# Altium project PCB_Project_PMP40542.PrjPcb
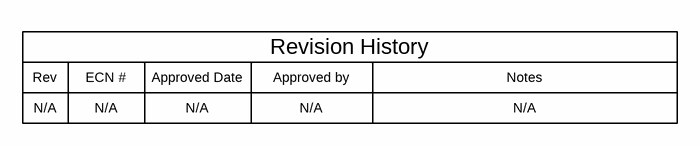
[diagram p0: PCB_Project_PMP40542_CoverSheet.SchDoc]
CopyrightYear: 2018; PCB_Layout: San Chen; PCB_Rev: E1; PRJ_Customer: Public Release; PRJ_Engineer: San Chen; PRJ_Number: PMP40542; PRJ_Title: 6~36V in, Type-C+Type-C Charger; SCH_Rev: E1; TechSupport: http://www.ti.com/support; TID: N/A
2 sheets, 62 parts. Net scope: flat (ports and power ports of the same name join across sheets).
Board file: PCB_Project_PMP40542_PCB.PcbDoc
Sheets:
  PCB_Project_PMP40542_CoverSheet.SchDoc
  PCB_Project_PMP40542_BlankSheet.SchDoc

## Sheet PCB_Project_PMP40542_CoverSheet.SchDoc
size 431 x 279 mm; Date: Not shown in title block; ApprovedBy: Not shown in title block; CheckedBy: Not shown in title block; Author: Not shown in title block; CompanyName: Not shown in title block; Engineer: Not shown in title block; Organization: Not shown in title block; Address1: Not shown in title block; Address2: Not shown in title block; Address3: Not shown in title block; Address4: Not shown in title block; DocumentNumber: 1; Revision: Use project parameter SCH_Rev; SheetNumber: 1; SheetTotal: 2; PageSetup: Record=PageOptions¦CenterHorizontal=True¦CenterVertical=True¦PrintScale=1.00¦XCorrection=1.00¦YCorrection=1.00¦PrintKind=0¦BorderSize=5000000¦LeftOffset=0¦BottomOffset=0¦Orientation=2¦PaperLength=1000¦PaperWidth=1000¦Scale=100¦PaperSource=15¦PrintQuality=600¦MediaType=1¦DitherType=10¦PaperKind=Letter¦PrintScaleMode=1

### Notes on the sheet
- Rev
- N/A
- ECN #
- Approved Date
- Approved by
- Revision History
- Notes

## Sheet PCB_Project_PMP40542_BlankSheet.SchDoc
size 431 x 279 mm; Date: Not shown in title block; ApprovedBy: Not shown in title block; CheckedBy: Not shown in title block; Author: Not shown in title block; CompanyName: Not shown in title block; Engineer: Not shown in title block; Organization: Not shown in title block; Address1: Not shown in title block; Address2: Not shown in title block; Address3: Not shown in title block; Address4: Not shown in title block; DocumentNumber: 1; Revision: Use project parameter SCH_Rev; SheetNumber: 2; SheetTotal: 2; PageSetup: Record=PageOptions¦CenterHorizontal=True¦CenterVertical=True¦PrintScale=1.00¦XCorrection=1.00¦YCorrection=1.00¦PrintKind=0¦BorderSize=5000000¦LeftOffset=0¦BottomOffset=0¦Orientation=2¦PaperLength=1000¦PaperWidth=1000¦Scale=100¦PaperSource=15¦PrintQuality=600¦MediaType=1¦DitherType=10¦PaperKind=Letter¦PrintScaleMode=1
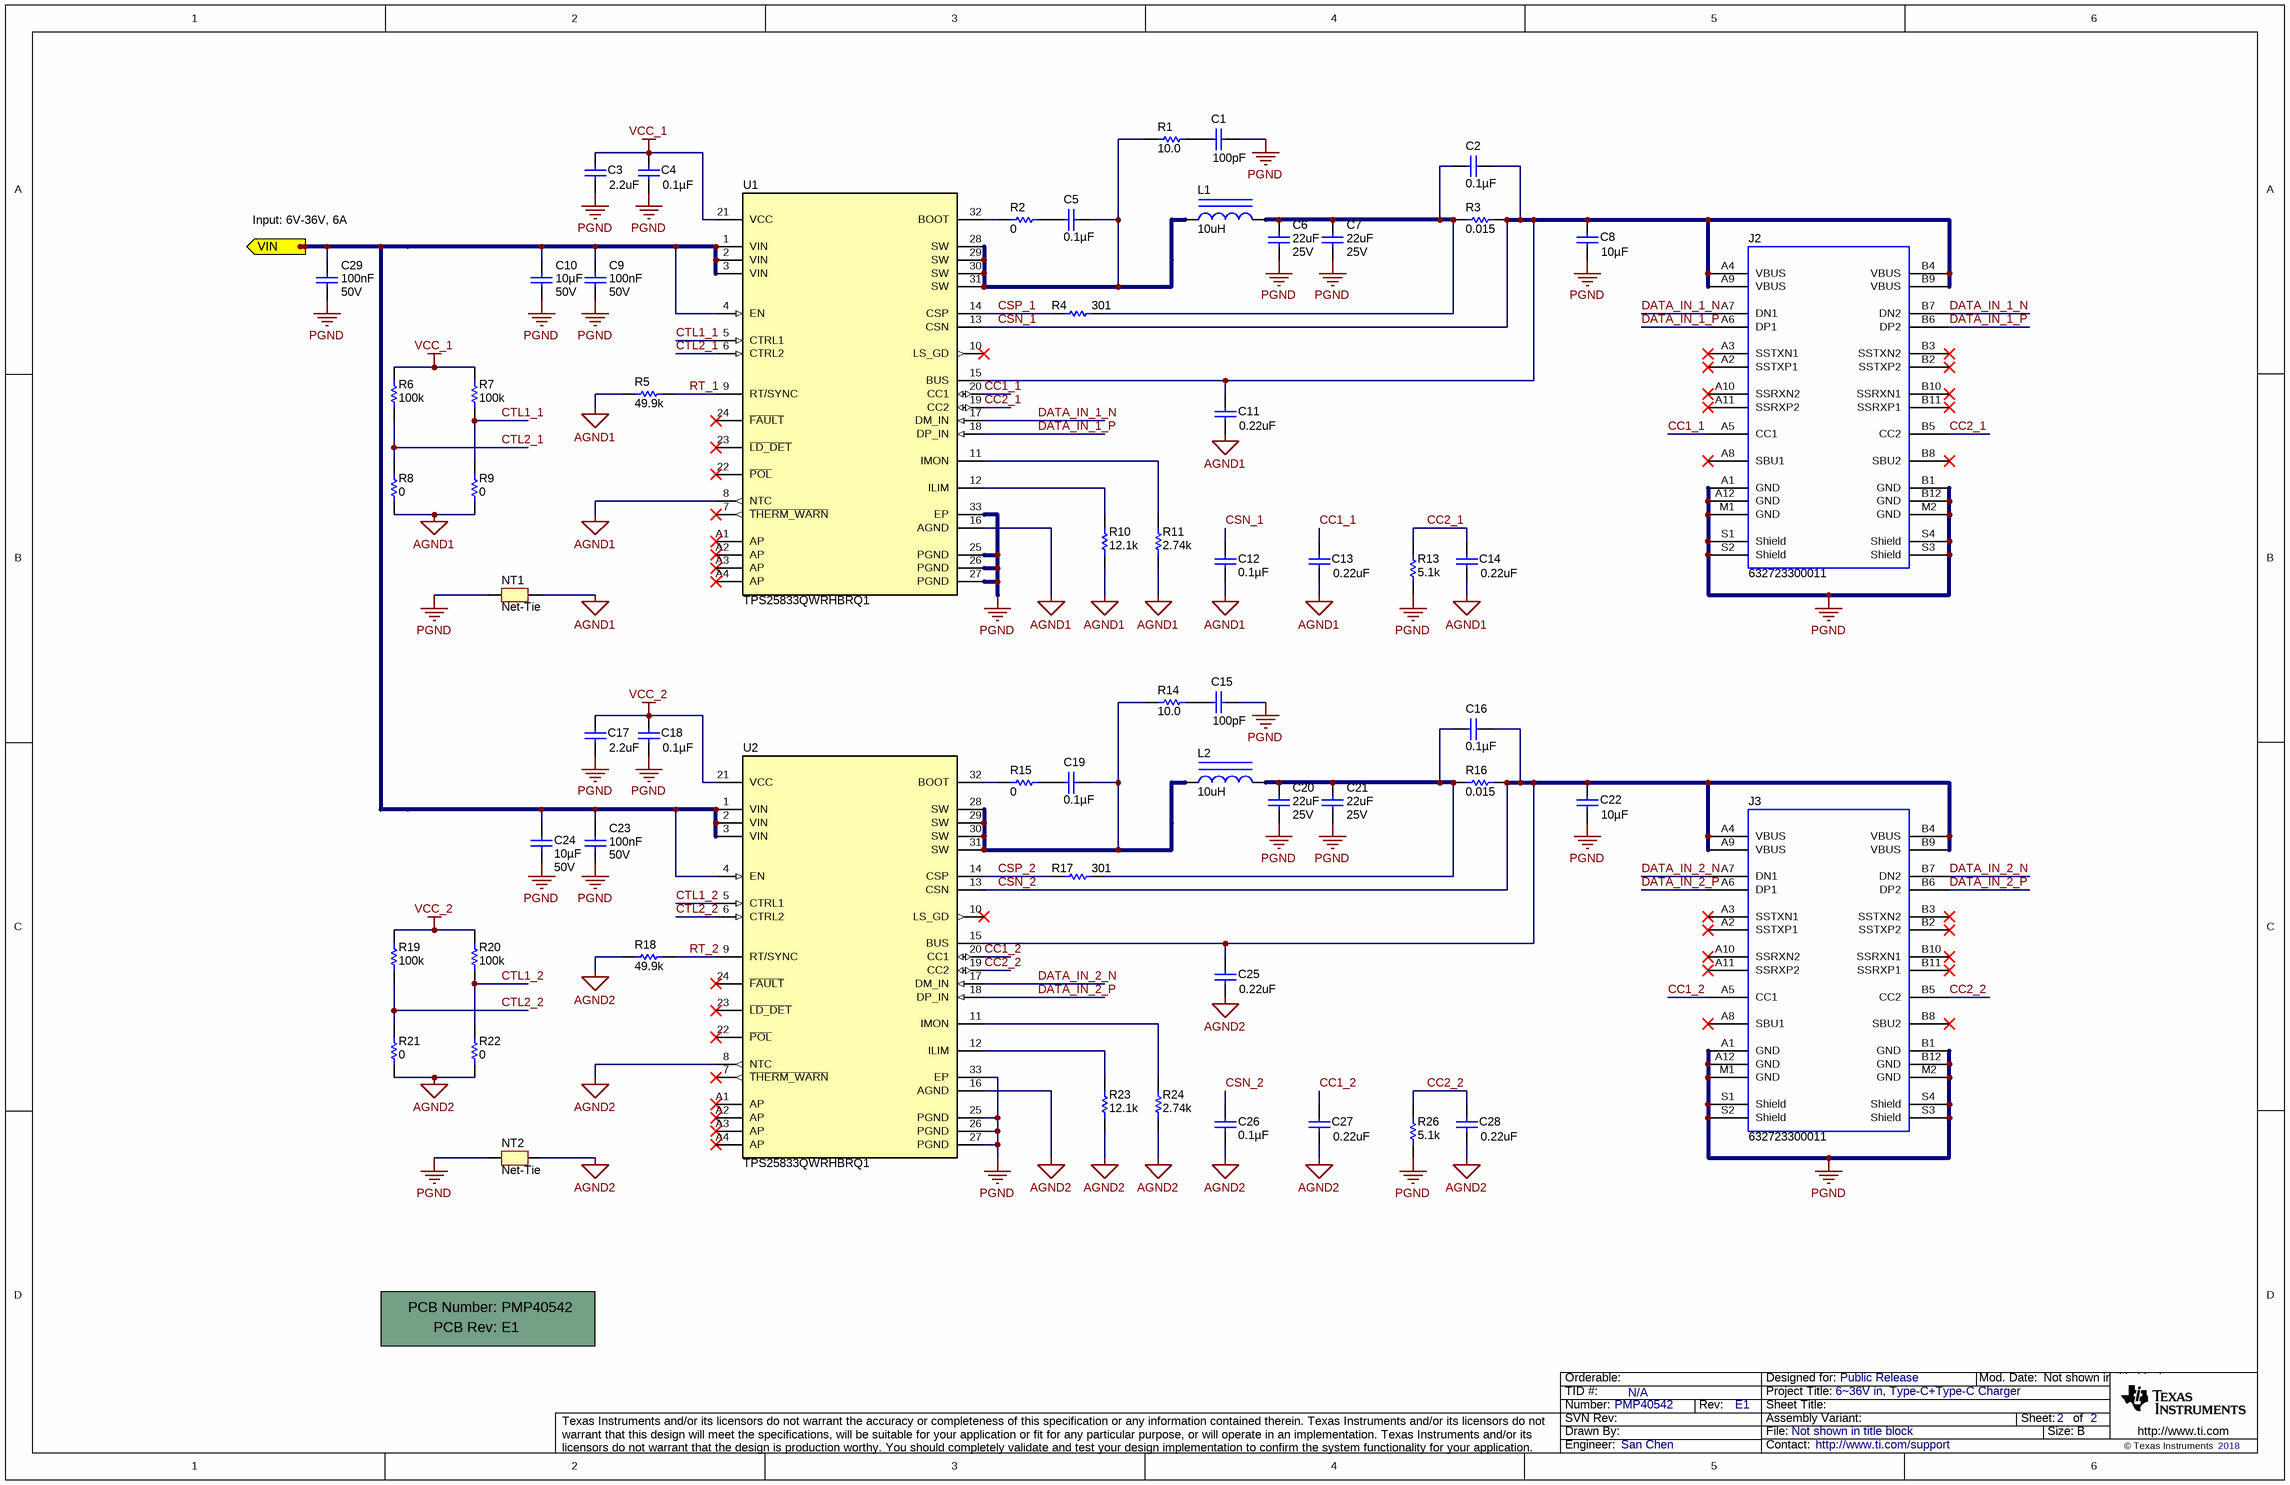
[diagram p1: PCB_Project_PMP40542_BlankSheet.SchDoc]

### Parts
!PCB  Printed Circuit Board  (value not drawn)  (mechanical)
C1  ValueDisplayed: 100pF  [0603]  (hidden comment: GCM1885C2A101JA16D)
C2  ValueDisplayed: 0.1µF  [0402]  (hidden comment: CGA2B3X7R1E104K050BB)
C3  ValueDisplayed: 2.2uF  [0402]  (hidden comment: GRT155R61E225KE13D)
C4  ValueDisplayed: 0.1µF  [0402]  (hidden comment: CGA2B3X7R1E104K050BB)
C5  ValueDisplayed: 0.1µF  [0402]  (hidden comment: CGA2B3X7R1E104K050BB)
C6  VDC_V: 25V  ValueDisplayed: 22uF  [1206_180]  (hidden comment: GRT31CR61E226KE01L)
C7  VDC_V: 25V  ValueDisplayed: 22uF  [1206_180]  (hidden comment: GRT31CR61E226KE01L)
C8  ValueDisplayed: 10µF  [0805_HV]  (hidden comment: GRM21BC81C106KA73L)
C9  Cap_F: 100nF  VDC_V: 50V  [0603]  (hidden comment: CGA3E2X7R1H104K080AA)
C10  ValueDisplayed: 10µF  VDC_V: 50V  [1206_190]  (hidden comment: CGA5L1X7R1H106K160AC)
C11  ValueDisplayed: 0.22uF  [0402]  (hidden comment: C1005X5R1E224M050BC)
C12  ValueDisplayed: 0.1µF  [0402]  (hidden comment: CGA2B3X7R1E104K050BB)
C13  ValueDisplayed: 0.22uF  [0402]  (hidden comment: C1005X5R1E224M050BC)
C14  ValueDisplayed: 0.22uF  [0402]  (hidden comment: C1005X5R1E224M050BC)
C15  ValueDisplayed: 100pF  [0603]  (hidden comment: GCM1885C2A101JA16D)
C16  ValueDisplayed: 0.1µF  [0402]  (hidden comment: CGA2B3X7R1E104K050BB)
C17  ValueDisplayed: 2.2uF  [0402]  (hidden comment: GRT155R61E225KE13D)
C18  ValueDisplayed: 0.1µF  [0402]  (hidden comment: CGA2B3X7R1E104K050BB)
C19  ValueDisplayed: 0.1µF  [0402]  (hidden comment: CGA2B3X7R1E104K050BB)
C20  VDC_V: 25V  ValueDisplayed: 22uF  [1206_180]  (hidden comment: GRT31CR61E226KE01L)
C21  VDC_V: 25V  ValueDisplayed: 22uF  [1206_180]  (hidden comment: GRT31CR61E226KE01L)
C22  ValueDisplayed: 10µF  [0805_HV]  (hidden comment: GRM21BC81C106KA73L)
C23  Cap_F: 100nF  VDC_V: 50V  [0603]  (hidden comment: CGA3E2X7R1H104K080AA)
C24  ValueDisplayed: 10µF  VDC_V: 50V  [1206_190]  (hidden comment: CGA5L1X7R1H106K160AC)
C25  ValueDisplayed: 0.22uF  [0402]  (hidden comment: C1005X5R1E224M050BC)
C26  ValueDisplayed: 0.1µF  [0402]  (hidden comment: CGA2B3X7R1E104K050BB)
C27  ValueDisplayed: 0.22uF  [0402]  (hidden comment: C1005X5R1E224M050BC)
C28  ValueDisplayed: 0.22uF  [0402]  (hidden comment: C1005X5R1E224M050BC)
C29  Cap_F: 100nF  VDC_V: 50V  [0603]  (hidden comment: CGA3E2X7R1H104K080AA)
J2  632723300011  [Wurth_632_723_300_011]
J3  632723300011  [Wurth_632_723_300_011]
L1  ValueDisplayed: 10uH  [XAL6060]  (hidden comment: XAL6060-103MEB)
L2  ValueDisplayed: 10uH  [XAL6060]  (hidden comment: XAL6060-103MEB)
NT1  Net-Tie  [Net-Tie_10milWide_30milLong]  (net tie, no BOM)
NT2  Net-Tie  [Net-Tie_10milWide_30milLong]  (net tie, no BOM)
R1  ValueDisplayed: 10.0  [1206]  (hidden comment: ERJ-8ENF10R0V)
R2  ValueDisplayed: 0  [0402]  (hidden comment: ERJ-2GE0R00X)
R3  ValueDisplayed: 0.015  [1206]  (hidden comment: CSR1206FK15L0)
R4  ValueDisplayed: 301  [0402]  (hidden comment: CRCW0402301RFKED)
R5  ValueDisplayed: 49.9k  [0402]  (hidden comment: ERJ-2RKF4992X)
R6  ValueDisplayed: 100k  [0402]  (hidden comment: CRCW0402100KFKED)
R7  ValueDisplayed: 100k  [0402]  (hidden comment: CRCW0402100KFKED)
R8  ValueDisplayed: 0  [0402]  (hidden comment: ERJ-2GE0R00X)
R9  ValueDisplayed: 0  [0402]  (hidden comment: ERJ-2GE0R00X)
R10  ValueDisplayed: 12.1k  [0402]  (hidden comment: CRCW040212K1FKED)
R11  ValueDisplayed: 2.74k  [0402]  (hidden comment: CRCW04022K74FKED)
R13  ValueDisplayed: 5.1k  [0402]  (hidden comment: CRCW04025K10JNED)
R14  ValueDisplayed: 10.0  [1206]  (hidden comment: ERJ-8ENF10R0V)
R15  ValueDisplayed: 0  [0402]  (hidden comment: ERJ-2GE0R00X)
R16  ValueDisplayed: 0.015  [1206]  (hidden comment: CSR1206FK15L0)
R17  ValueDisplayed: 301  [0402]  (hidden comment: CRCW0402301RFKED)
R18  ValueDisplayed: 49.9k  [0402]  (hidden comment: ERJ-2RKF4992X)
R19  ValueDisplayed: 100k  [0402]  (hidden comment: CRCW0402100KFKED)
R20  ValueDisplayed: 100k  [0402]  (hidden comment: CRCW0402100KFKED)
R21  ValueDisplayed: 0  [0402]  (hidden comment: ERJ-2GE0R00X)
R22  ValueDisplayed: 0  [0402]  (hidden comment: ERJ-2GE0R00X)
R23  ValueDisplayed: 12.1k  [0402]  (hidden comment: CRCW040212K1FKED)
R24  ValueDisplayed: 2.74k  [0402]  (hidden comment: CRCW04022K74FKED)
R26  ValueDisplayed: 5.1k  [0402]  (hidden comment: CRCW04025K10JNED)
U1  TPS25833QWRHBRQ1  [RHB0032R]
U2  TPS25833QWRHBRQ1  [RHB0032R]

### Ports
VIN (in)

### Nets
AGND1: C11.2 C12.1 C13.2 C14.2 NT1.2 R5.1 R8.1 R9.1 R10.1 R11.1 U1.8(NTC) U1.16(AGND)
AGND2: C25.2 C26.1 C27.2 C28.2 NT2.2 R18.1 R21.1 R22.1 R23.1 R24.1 U2.8(NTC) U2.16(AGND)
PGND: C1.1 C3.2 C4.2 C6.2 C7.2 C8.2 C9.2 C10.2 C15.1 C17.2 C18.2 C20.2 C21.2 C22.2 C23.2 C24.2 C29.2 J2.A1(GND) J2.A12(GND) J2.B1(GND) J2.B12(GND) J2.M1(GND) J2.M2(GND) J2.S1(Shield) J2.S2(Shield) J2.S3(Shield) J2.S4(Shield) J3.A1(GND) J3.A12(GND) J3.B1(GND) J3.B12(GND) J3.M1(GND) J3.M2(GND) J3.S1(Shield) J3.S2(Shield) J3.S3(Shield) J3.S4(Shield) NT1.1 NT2.1 R13.1 R26.1 U1.25(PGND) U1.26(PGND) U1.27(PGND) U1.33(EP) U2.25(PGND) U2.26(PGND) U2.27(PGND) U2.33(EP)
VCC_1: C3.1 C4.1 R6.2 R7.2 U1.21(VCC)
VCC_2: C17.1 C18.1 R19.2 R20.2 U2.21(VCC)
CC1_1: C13.1 J2.A5(CC1) U1.20(CC1)
CC1_2: C27.1 J3.A5(CC1) U2.20(CC1)
CC2_1: C14.1 J2.B5(CC2) R13.2 U1.19(CC2)
CC2_2: C28.1 J3.B5(CC2) R26.2 U2.19(CC2)
CSN_1: C2.2 C8.1 C11.1 C12.2 J2.A4(VBUS) J2.A9(VBUS) J2.B4(VBUS) J2.B9(VBUS) R3.2 U1.13(CSN) U1.15(BUS)
CSN_2: C16.2 C22.1 C25.1 C26.2 J3.A4(VBUS) J3.A9(VBUS) J3.B4(VBUS) J3.B9(VBUS) R16.2 U2.13(CSN) U2.15(BUS)
CSP_1: R4.1 U1.14(CSP)
CSP_2: R17.1 U2.14(CSP)
CTL1_1: R7.1 R9.2 U1.5(CTRL1)
CTL1_2: R20.1 R22.2 U2.5(CTRL1)
CTL2_1: R6.1 R8.2 U1.6(CTRL2)
CTL2_2: R19.1 R21.2 U2.6(CTRL2)
DATA_IN_1_N: J2.A7(DN1) J2.B7(DN2) U1.17(DM_IN)
DATA_IN_1_P: J2.A6(DP1) J2.B6(DP2) U1.18(DP_IN)
DATA_IN_2_N: J3.A7(DN1) J3.B7(DN2) U2.17(DM_IN)
DATA_IN_2_P: J3.A6(DP1) J3.B6(DP2) U2.18(DP_IN)
RT_1: R5.2 U1.9(RT/SYNC)
RT_2: R18.2 U2.9(RT/SYNC)
VIN: C9.1 C10.1 C23.1 C24.1 C29.1 U1.1(VIN) U1.2(VIN) U1.3(VIN) U1.4(EN) U2.1(VIN) U2.2(VIN) U2.3(VIN) U2.4(EN) ; port VIN
NetC1_2: C1.2 R1.2
NetC2_1: C2.1 C6.1 C7.1 L1.2 R3.1 R4.2
NetC5_1: C5.1 R2.2
NetC5_2: C5.2 L1.1 R1.1 U1.28(SW) U1.29(SW) U1.30(SW) U1.31(SW)
NetC15_2: C15.2 R14.2
NetC16_1: C16.1 C20.1 C21.1 L2.2 R16.1 R17.2
NetC19_1: C19.1 R15.2
NetC19_2: C19.2 L2.1 R14.1 U2.28(SW) U2.29(SW) U2.30(SW) U2.31(SW)
NetR2_1: R2.1 U1.32(BOOT)
NetR10_2: R10.2 U1.12(ILIM)
NetR11_2: R11.2 U1.11(IMON)
NetR15_1: R15.1 U2.32(BOOT)
NetR23_2: R23.2 U2.12(ILIM)
NetR24_2: R24.2 U2.11(IMON)

Not connected (* = marked no-connect by the designer): J2 A2(SSTXP1)* A3(SSTXN1)* A8(SBU1)* A10(SSRXN2)* A11(SSRXP2)* B2(SSTXP2)* B3(SSTXN2)* B8(SBU2)* B10(SSRXN1)* B11(SSRXP1)*; J3 A2(SSTXP1)* A3(SSTXN1)* A8(SBU1)* A10(SSRXN2)* A11(SSRXP2)* B2(SSTXP2)* B3(SSTXN2)* B8(SBU2)* B10(SSRXN1)* B11(SSRXP1)*; U1 7(~{THERM_WARN})* 10(LS_GD)* 22(~{POL})* 23(~{LD_DET})* 24(~{FAULT})* A1(AP)* A2(AP)* A3(AP)* A4(AP)*; U2 7(~{THERM_WARN})* 10(LS_GD)* 22(~{POL})* 23(~{LD_DET})* 24(~{FAULT})* A1(AP)* A2(AP)* A3(AP)* A4(AP)*

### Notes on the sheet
- (near C29) Input: 6V-36V, 6A

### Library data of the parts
!PCB = CMP-0003618-2: Manufacturer: Any; PartNumber: PMP40542
C1 C15 = CMP-0007130-4: CAP, CERM, 100 pF, 100 V, +/- 5%, C0G/NP0, AEC-Q200 Grade 1, 0603; Manufacturer: MuRata; TaMin_C: -55°C; Polarized: N; SizeAreaWB_mm2: 4.68; Value1: Unknown; U/M: EA; TaMax_C: 125°C; SizeZ_mm: 1; SizeX_mm: 1.6; SizeY_mm: 0.8; Value2: 100V; SizeArea_mm2: 1.28; CompType: Capacitor; AEC Qualified: Y; AEC Category: Q200; Value: 100pF
C2 C4 C5 C12 C16 C18 C19 C26 = CMP-0080610-1: CAP, CERM, 0.1 µF, 25 V,+/- 10%, X7R, AEC-Q200 Grade 1, 0402; Manufacturer: TDK; TaMin_C: -55°C; Polarized: N; SizeAreaWB_mm2: 3; U/M: EA; Value: 0.1uF; TaMax_C: 125°C; SizeZ_mm: 0.6; SizeX_mm: 1; SizeY_mm: 0.5; Value2: 25V; CompType: Capacitor; AEC Qualified: Y; Cap_F: 100nF; AEC Category: Q200
C3 C17 = CMP-0006716-2: CAP, CERM, 2.2 uF, 25 V, +/- 10%, X5R, AEC-Q200 Grade 3, 0402; Manufacturer: MuRata; TaMin_C: -55°C; Polarized: N; SizeAreaWB_mm2: 3; Value1: Unknown; U/M: EA; Value: 2.2uF; TaMax_C: 85°C; SizeZ_mm: 0.6; SizeX_mm: 1; SizeY_mm: 0.5; Value2: 25V; CompType: Capacitor; AEC Qualified: Y; Cap_F: 2.2µF; AEC Category: Q200
C6 C7 C20 C21 = CMP-0009014-2: CAP, CERM, 22 uF, 25 V, +/- 10%, X5R, AEC-Q200 Grade 3, 1206; Manufacturer: MuRata; TaMin_C: -55°C; Polarized: N; SizeAreaWB_mm2: 10.92; Value1: Unknown; U/M: EA; Value: 22uF; TaMax_C: 85°C; SizeZ_mm: 1.8; SizeX_mm: 3.2; SizeY_mm: 1.6; Cap_Case: 1206; SizeArea_mm2: 5.12; AEC Qualified: Y; Cap_F: 22µF; AEC Grade: 3; AEC Category: Q200
C8 C22 = CMP-0081634-1: CAP, CERM, 10 µF, 16 V,+/- 10%, X6S, 0805; Manufacturer: MuRata; TaMin_C: -55°C; ESR_ohm: 1m; Polarized: N; SizeAreaWB_mm2: 6.75; Value1: 0.001 ohm; U/M: EA; Value: 10uF; TaMax_C: 105°C; SizeZ_mm: 1.45; SizeX_mm: 2; SizeY_mm: 1.25; Cap_Case: 0805; Value2: 16V; SizeArea_mm2: 2.5; CompType: Capacitor; IRMS_A: 6A; AEC Category: Q200
C9 C23 C29 = CMP-0007078-4: CAP, CERM, 0.1 uF, 50 V, +/- 10%, X7R, AEC-Q200 Grade 1, 0603; Manufacturer: TDK; TaMin_C: -55°C; ESR_ohm: 0.0296; Polarized: N; SizeAreaWB_mm2: 4.68; Value1: 0.0296 ohm; U/M: EA; Value: 0.1uF; TaMax_C: 125°C; SizeZ_mm: 1; SizeX_mm: 1.6; SizeY_mm: 0.8; SizeArea_mm2: 1.28; AEC Qualified: Y; IRMS_A: 9.7199dA; AEC Category: Q200
C10 C24 = CMP-0085950-1: CAP, CERM, 10 µF, 50 V,+/- 10%, X7R, AEC-Q200 Grade 1, 1206; Manufacturer: TDK; SizeZ_mm: 1.9; Value: 10uF; Cap_Case: 1206; AEC Grade: 1; TaMin_C: -55°C; U/M: EA; SizeArea_mm2: 5.12; TaMax_C: 125°C; AEC Qualified: Y; AEC Category: Q200; SizeX_mm: 3.2; SizeY_mm: 1.6; Polarized: N; SizeAreaWB_mm2: 10.92
C11 C13 C14 C25 C27 C28 = CMP-0006277-2: CAP, CERM, 0.22 uF, 25 V, +/- 20%, X5R, 0402; Manufacturer: TDK; TaMin_C: -55°C; Polarized: N; SizeAreaWB_mm2: 3; Value1: Unknown; U/M: EA; Value: 0.22uF; TaMax_C: 85°C; SizeZ_mm: 0.6; SizeX_mm: 1; SizeY_mm: 0.5; Value2: 25V; CompType: Capacitor; Cap_F: 220nF; AEC Category: Q200
J2 J3 = CMP-0080891-1: Connector, Receptacle, USB Type C, R/A; Manufacturer: Wurth Elektronik; Current_A: 3A; Gender: Female; Voltage_V: 5V; ContactFinish: Gold; Cert_UL: Y
L1 L2 = CMP-0061019-2: Inductor, Shielded, Composite, 10 µH, 7 A, 0.02982 ohm, AEC-Q200 Grade 1, SMD; Manufacturer: Coilcraft; Irms: 9.2A @ 40C rise; Green_REACh: Incomplete; Imax_A: 7.6A; SizeX_mm: 6.36; Value: 10uH; Ind_H: 10µH; AEC Category: Q200; AEC Qualified: Y; SizeArea_mm2: 41.7216; SizeZ_mm: 6.1; Isat: 7.6A @ 30% inductance drop; Green_Lifecycle: Not Set; AEC Grade: 1; SizeAreaWB_mm2: 71.5616; SizeY_mm: 6.56
NT1 NT2 = CMP-0078142-2: Single point connection between nets.
R1 R14 = CMP-0017299-3: RES, 10.0, 1%, 0.25 W, AEC-Q200 Grade 0, 1206; Manufacturer: Panasonic; Power_W: 250mW; TempCo: 100 ppm/C; Value_Code: 10R0; Value: 10.0; EIA_Code: E96; Res_ohm: 10; SizeX_mm: 3.2; SizeY_mm: 1.6; SizeZ_mm: 1.35; Value2: 0.25W; SizeArea_mm2: 5.12; AEC Qualified: Y; VDC_V: 200V; AEC Category: Q200; AEC Grade: 0; SizeAreaWB_mm2: 10.92
R2 R8 R9 R15 R21 R22 = CMP-0026992-3: RES, 0, 5%, 0.1 W, AEC-Q200 Grade 0, 0402; Manufacturer: Panasonic; Power_W: 100mW; TempCo: 600 ppm/C; Value_Code: 0000; Value: 0; EIA_Code: E24; SizeX_mm: 1; SizeY_mm: 0.5; SizeZ_mm: 0.6; Value2: 0.1W; AEC Qualified: Y; VDC_V: 50V; AEC Category: Q200; SizeAreaWB_mm2: 3
R3 = CMP-0017258-2: RES, 0.015, 1%, 0.5 W, 1206; Manufacturer: Stackpole Electronics Inc; Power_W: 500mW; TempCo: 100 ppm/C; Value_Code: R015; U/M: EA; Value: 0.015; EIA_Code: E96; SizeX_mm: 3.2; SizeY_mm: 1.6; SizeZ_mm: 1.35; Value2: 0.5W; SizeArea_mm2: 5.12; CompType: Resistor; AEC Category: Q200
R4 R17 = CMP-0026281-2: RES, 301, 1%, 0.063 W, AEC-Q200 Grade 0, 0402; Manufacturer: Vishay-Dale; Power_W: 63mW; TempCo: 100 ppm/C; Value_Code: 301R; Value: 301; EIA_Code: E96; SizeX_mm: 1; SizeY_mm: 0.5; SizeZ_mm: 0.6; Value2: 0.063W; AEC Qualified: Y; VDC_V: 50V; AEC Category: Q200; AEC Grade: 0
R5 R18 = CMP-0026702-1: RES, 49.9 k, 1%, 0.1 W, AEC-Q200 Grade 0, 0402; Manufacturer: Panasonic; Power_W: 100mW; TempCo: 100 ppm/C; Value_Code: 49k9; U/M: EA; Value: 49.9k; EIA_Code: E96; SizeX_mm: 1; SizeY_mm: 0.5; SizeZ_mm: 0.6; Value2: 0.1W; AEC Qualified: Y; VDC_V: 50V; AEC Grade: 0; AEC Category: Q200
R6 R7 R19 R20 = CMP-0025950-3: RES, 100 k, 1%, 0.063 W, AEC-Q200 Grade 0, 0402; Manufacturer: Vishay-Dale; Power_W: 63mW; TempCo: 100 ppm/C; Value: 100k; EIA_Code: E96; SizeX_mm: 1; SizeY_mm: 0.5; SizeZ_mm: 0.6; Value2: 0.063W; AEC Qualified: Y; VDC_V: 50V; AEC Category: Q200; AEC Grade: 0
R10 R23 = CMP-0025991-3: RES, 12.1 k, 1%, 0.063 W, AEC-Q200 Grade 0, 0402; Manufacturer: Vishay-Dale; Power_W: 63mW; TempCo: 100 ppm/C; Value_Code: 12k1; Value: 12.1k; EIA_Code: E96; SizeX_mm: 1; SizeY_mm: 0.5; SizeZ_mm: 0.6; Value2: 0.063W; AEC Qualified: Y; VDC_V: 50V; AEC Category: Q200; AEC Grade: 0
R11 R24 = CMP-0026241-2: RES, 2.74 k, 1%, 0.063 W, AEC-Q200 Grade 0, 0402; Manufacturer: Vishay-Dale; Power_W: 63mW; TempCo: 100 ppm/C; Value_Code: 2k74; Value: 2.74k; EIA_Code: E96; SizeX_mm: 1; SizeY_mm: 0.5; SizeZ_mm: 0.6; Value2: 0.063W; AEC Qualified: Y; VDC_V: 50V; AEC Category: Q200; AEC Grade: 0
R13 R26 = CMP-0026951-5: RES, 5.1 k, 5%, 0.063 W, AEC-Q200 Grade 0, 0402; Manufacturer: Vishay-Dale; Power_W: 63mW; TempCo: 200 ppm/C; Value_Code: 5k10; Value: 5.1k; EIA_Code: E24; SizeX_mm: 1; SizeY_mm: 0.5; SizeZ_mm: 0.6; Value2: 0.063W; AEC Qualified: Y; VDC_V: 50V; AEC Category: Q200; AEC Grade: 0
R16 = CMP-0017258-2: RES, 0.015, 1%, 0.5 W, 1206; Manufacturer: Stackpole Electronics Inc; Power_W: 500mW; TempCo: 100 ppm/C; Value_Code: R015; U/M: EA; Value: 0.015; EIA_Code: E96; SizeX_mm: 3.2; SizeY_mm: 1.6; SizeZ_mm: 1.35; Value2: 0.5W; SizeArea_mm2: 5.12; AEC Category: Q200
U1 U2 = CMP-0079842-1: USB Type-C and BC1.2 5V 3.5A Output, 36V Input Synchronous Buck with Cable Compensation, RHB0032R (VQFN-32); Alternate Manufacturer: Texas Instruments; SizeAreaWB_mm2: 49; SizeZ_mm: 1; SizeX_mm: 5; SizeArea_mm2: 25; CompType: IC; AEC Qualified: Y; AEC Category: Q200

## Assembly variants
001: not fitted C1 C15 FID1 FID2 FID3 R1 R8 R9 R12 R13 R14 R21 R22 R25 R26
